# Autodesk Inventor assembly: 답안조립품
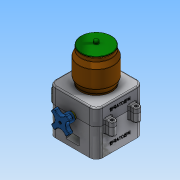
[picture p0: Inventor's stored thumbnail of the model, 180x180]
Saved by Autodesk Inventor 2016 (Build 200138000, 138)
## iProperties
Created: 2018-01
Part Number: 답안조립품
Material: 일반
Document SubType Name: Assembly
Designer: Administrator
Author: Administrator
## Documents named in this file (9)
- C:\Users\Administrator\Desktop\480107V1018\답안조립품.iam
- C:\Users\Administrator\Desktop\480107V1018\본체.ipt
- C:\Users\Administrator\Desktop\480107V1018\볼트 M3x12.ipt
- C:\Users\Administrator\Desktop\480107V1018\핸들.ipt
- C:\Users\Administrator\Desktop\480107V1018\핸들축.ipt
- C:\Users\Administrator\Desktop\480107V1018\본체커버.ipt
- C:\Users\Administrator\Desktop\480107V1018\볼트 M4x12.ipt
- C:\Users\Administrator\Desktop\480107V1018\용기.ipt
- C:\Users\Administrator\Desktop\480107V1018\용기캡.ipt
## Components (2 placed, 2 different names)
1. 핸들:1
2. 핸들축:1
